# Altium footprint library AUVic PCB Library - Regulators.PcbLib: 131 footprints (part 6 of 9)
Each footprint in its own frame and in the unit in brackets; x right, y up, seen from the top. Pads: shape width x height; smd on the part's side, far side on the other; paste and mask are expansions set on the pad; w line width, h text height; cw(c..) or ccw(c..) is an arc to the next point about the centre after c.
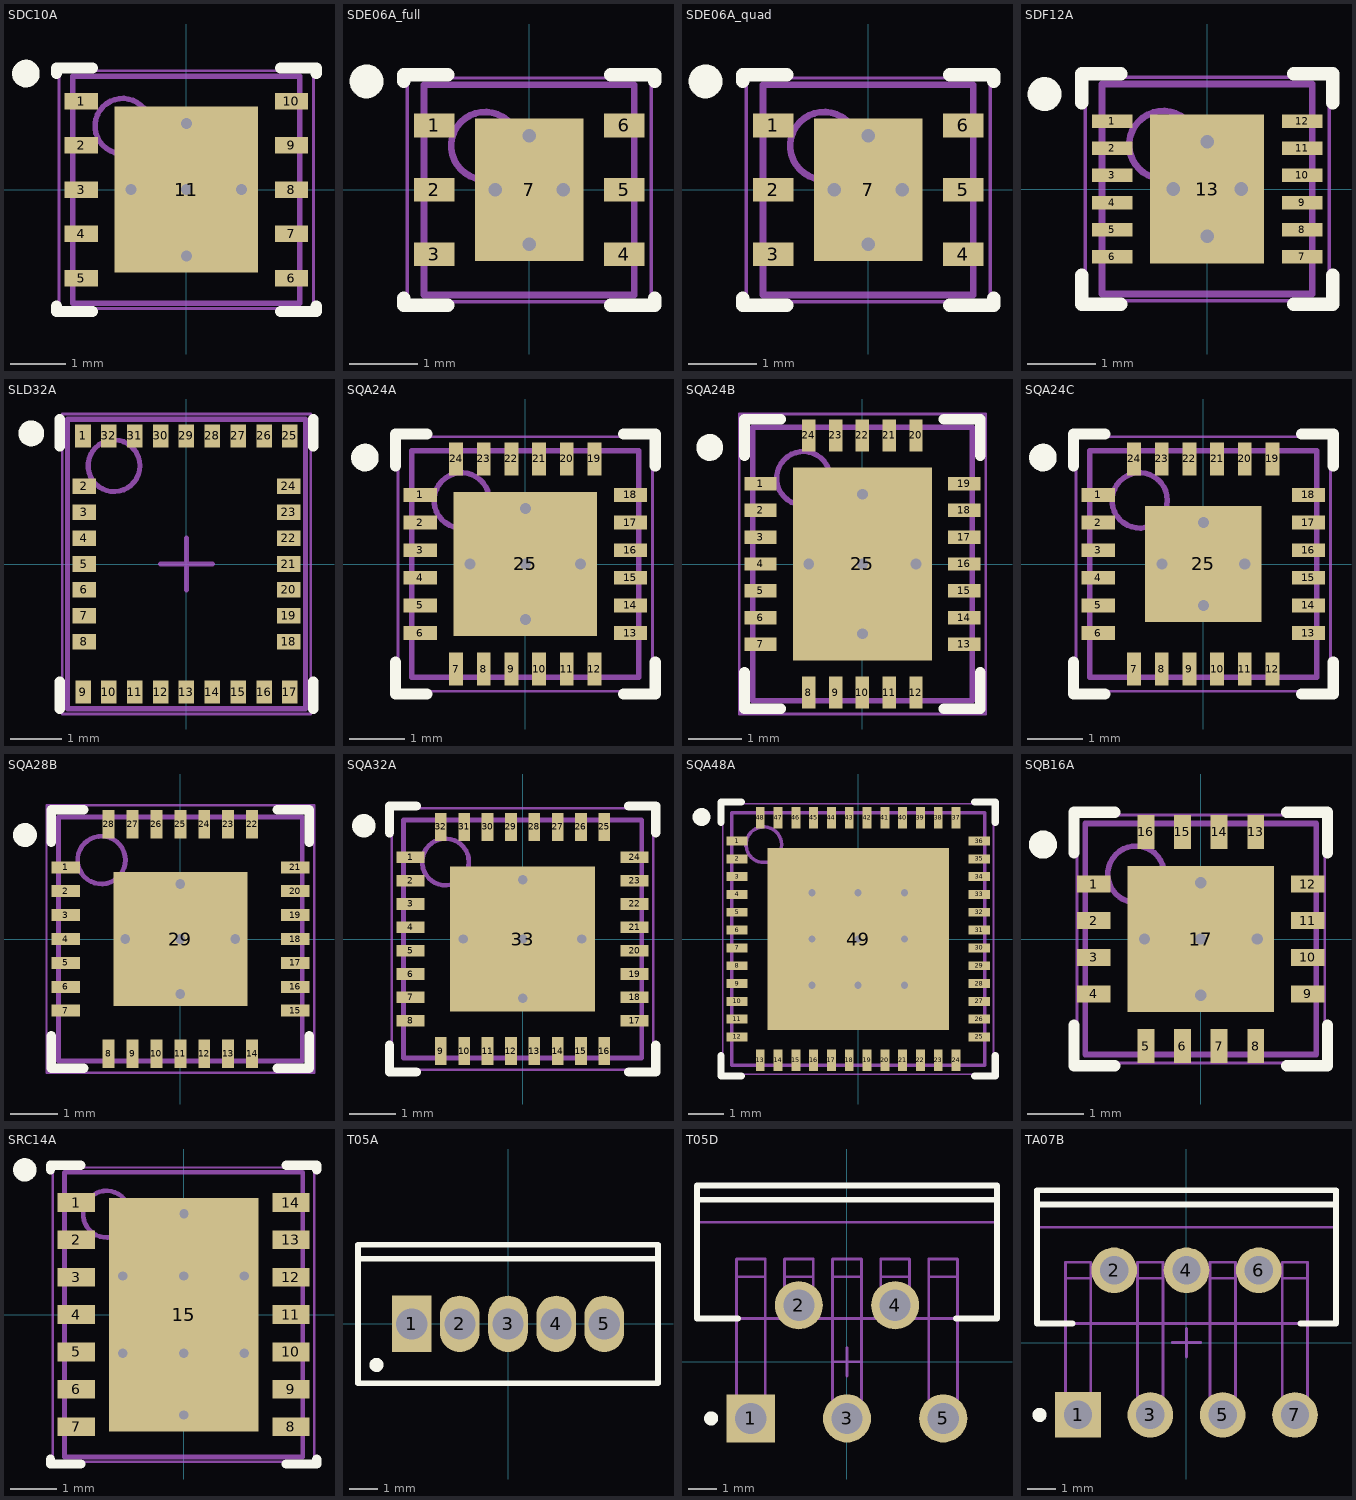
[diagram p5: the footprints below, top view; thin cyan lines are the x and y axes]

## SDC10A [mm] "SON, 10-Leads, Body 4x4 mm, Pitch 0.8mm, NSC Recommended"
height 0.8
pads (11):
  rect 0.6x0.3 smd paste-0.15 mask+0.051: 1(-1.9,1.6) 2(-1.9,0.8) 3(-1.9,0) 4(-1.9,-0.8) 5(-1.9,-1.6) 6(1.9,-1.6) 7(1.9,-0.8) 8(1.9,0) 9(1.9,0.8) 10(1.9,1.6)
  rect 2.6x3 smd paste-1.3 mask+0.051: 11(0,0)
via -1,0 diameter 0.5 hole 0.2
via 0,-1.2 diameter 0.5 hole 0.2
via 0,0 diameter 0.5 hole 0.2
via 0,1.2 diameter 0.5 hole 0.2
via 1,0 diameter 0.5 hole 0.2
Top Overlay:
  circle w0.25: c-2.9,2.1 r0.125
  lines w0.2: -2.35,-2.2 -2.35,-2.1 ; -2.35,2.1 -2.35,2.2 ; -2.345,-2.2 -1.7,-2.2 ; -2.345,2.2 -1.7,2.2 ; 1.7,-2.2 2.345,-2.2 ; 1.7,2.2 2.345,2.2 ; 2.35,-2.2 2.35,-2.1 ; 2.35,2.1 2.35,2.2
Top Paste:
  rectangle: 0.1,-1.4 1.2,-0.1
  region: -0.1,-0.1 -1.2,-0.1 -1.2,-1.4 -0.1,-1.4
  region: -0.1,1.4 -1.2,1.4 -1.2,0.1 -0.1,0.1
  rectangle: 0.1,0.1 1.2,1.4
  rectangle: -2.4,1.45 -1.7,1.75
  rectangle: -2.4,0.65 -1.7,0.95
  rectangle: -2.4,-0.15 -1.7,0.15
  rectangle: -2.4,-0.95 -1.7,-0.65
  rectangle: -2.4,-1.75 -1.7,-1.45
  region: 2.4,-1.45 1.7,-1.45 1.7,-1.75 2.4,-1.75
  region: 2.4,-0.65 1.7,-0.65 1.7,-0.95 2.4,-0.95
  region: 2.4,0.15 1.7,0.15 1.7,-0.15 2.4,-0.15
  region: 2.4,0.95 1.7,0.95 1.7,0.65 2.4,0.65
  region: 2.4,1.75 1.7,1.75 1.7,1.45 2.4,1.45
Mechanical 13:
  circle w0.1: c-1.15,1.15 r0.5
  lines w0.1: -2.05,-2.05 2.05,-2.05 2.05,2.05 -2.05,2.05 -2.05,-2.05
Mechanical 15:
  lines w0.05: -2.3,-2.15 2.3,-2.15 2.3,2.15 -2.3,2.15 -2.3,-2.15
  lines w0.1: -0.5,0 0.5,0 ; 0,-0.5 0,0.5
3D body: height 0.8, standoff 0, extent -2.049,-2.049 2.049,2.049

## SDE06A_full [mm] "SON, 6-Leads, Body 3x3 mm, Pitch 0.95mm, NSC Recommended"
height 0.8
pads (7):
  rect 0.6x0.35 smd paste-0.175 mask+0.051: 1(-1.4,0.95) 2(-1.4,0) 3(-1.4,-0.95) 4(1.4,-0.95) 5(1.4,0) 6(1.4,0.95)
  rect 1.6x2.1 smd paste-0.8 mask+0.051: 7(0,0)
via 0,-0.8 diameter 0.5 hole 0.2
via 0.5,0 diameter 0.5 hole 0.2
via 0,0.8 diameter 0.5 hole 0.2
via -0.5,0 diameter 0.5 hole 0.2
Top Overlay:
  circle w0.25: c-2.4,1.6 r0.125
  lines w0.2: -1.85,-1.6 -1.85,-1.7 -1.2,-1.7 ; -1.85,1.6 -1.85,1.7 -1.2,1.7 ; 1.2,-1.7 1.85,-1.7 1.85,-1.6 ; 1.2,1.7 1.85,1.7 1.85,1.6
Top Paste:
  rectangle: -0.76,-1 0.76,1
  region: 1.9,1.125 1.2,1.125 1.2,0.775 1.9,0.775
  region: 1.9,0.175 1.2,0.175 1.2,-0.175 1.9,-0.175
  region: 1.9,-0.775 1.2,-0.775 1.2,-1.125 1.9,-1.125
  rectangle: -1.9,-1.125 -1.2,-0.775
  rectangle: -1.9,-0.175 -1.2,0.175
  rectangle: -1.9,0.775 -1.2,1.125
Mechanical 13:
  circle w0.1: c-0.65,0.65 r0.5
  lines w0.1: -1.55,-1.55 1.55,-1.55 1.55,1.55 -1.55,1.55 -1.55,-1.55
Mechanical 15:
  lines w0.05: -1.8,-1.65 -1.8,1.65 1.8,1.65 1.8,-1.65 -1.8,-1.65
  lines w0.1: -0.5,0 0.5,0 ; 0,-0.5 0,0.5
3D body: height 0.8, standoff 0, extent -1.55,-1.55 1.55,1.55

## SDE06A_quad [mm] "SON, 6-Leads, Body 3x3 mm, Pitch 0.95mm, NSC Recommended"
height 0.8
pads (7):
  rect 0.6x0.35 smd paste-0.175 mask+0.051: 1(-1.4,0.95) 2(-1.4,0) 3(-1.4,-0.95) 4(1.4,-0.95) 5(1.4,0) 6(1.4,0.95)
  rect 1.6x2.1 smd paste-0.8 mask+0.051: 7(0,0)
via -0.5,0 diameter 0.5 hole 0.2
via 0,0.8 diameter 0.5 hole 0.2
via 0.5,0 diameter 0.5 hole 0.2
via 0,-0.8 diameter 0.5 hole 0.2
Top Overlay:
  circle w0.25: c-2.4,1.6 r0.125
  lines w0.2: -1.85,-1.6 -1.85,-1.7 -1.2,-1.7 ; -1.85,1.6 -1.85,1.7 -1.2,1.7 ; 1.2,-1.7 1.85,-1.7 1.85,-1.6 ; 1.2,1.7 1.85,1.7 1.85,1.6
Top Paste:
  rectangle: -1.9,0.775 -1.2,1.125
  rectangle: -1.9,-0.175 -1.2,0.175
  rectangle: -1.9,-1.125 -1.2,-0.775
  region: 1.9,-0.775 1.2,-0.775 1.2,-1.125 1.9,-1.125
  region: 1.9,0.175 1.2,0.175 1.2,-0.175 1.9,-0.175
  region: 1.9,1.125 1.2,1.125 1.2,0.775 1.9,0.775
  region: -0.1,1.05 -0.8,1.05 -0.8,0.1 -0.1,0.1
  rectangle: 0.1,0.1 0.8,1.05
  rectangle: 0.1,-1.05 0.8,-0.1
  region: -0.1,-0.1 -0.8,-0.1 -0.8,-1.05 -0.1,-1.05
Mechanical 13:
  circle w0.1: c-0.65,0.65 r0.5
  lines w0.1: -1.55,-1.55 -1.55,1.55 1.55,1.55 1.55,-1.55 -1.55,-1.55
Mechanical 15:
  lines w0.05: -1.8,-1.65 1.8,-1.65 1.8,1.65 -1.8,1.65 -1.8,-1.65
  lines w0.1: -0.5,0 0.5,0 ; 0,-0.5 0,0.5
3D body: height 0.8, standoff 0, extent -1.55,-1.55 1.55,1.55

## SDF12A [mm] "SON, 12-Leads, Body 3x3mm, Pitch 0.4mm, NSC Recommended"
height 0.8
pads (13):
  rect 0.6x0.2 smd paste-0.125 mask+0.051: 1(-1.4,1) 2(-1.4,0.6) 3(-1.4,0.2) 4(-1.4,-0.2) 5(-1.4,-0.6) 6(-1.4,-1) 7(1.4,-1) 8(1.4,-0.6) 9(1.4,-0.2) 10(1.4,0.2) 11(1.4,0.6) 12(1.4,1)
  rect 1.68x2.2 smd paste-0.05 mask+0.051: 13(0,0)
via 0,-0.7 diameter 0.5 hole 0.2
via 0,0.7 diameter 0.5 hole 0.2
via 0.5,0 diameter 0.5 hole 0.2
via -0.5,0 diameter 0.5 hole 0.2
Top Overlay:
  circle w0.25: c-2.4,1.4 r0.125
  lines w0.2: -1.85,-1.275 -1.85,-1.7 -1.275,-1.7 ; -1.85,1.275 -1.85,1.7 -1.275,1.7 ; 1.275,-1.7 1.85,-1.7 1.85,-1.275 ; 1.275,1.7 1.85,1.7 1.85,1.275
Top Paste:
  rectangle: -1.9,0.9 -1.2,1.1
  rectangle: -1.9,0.5 -1.2,0.7
  rectangle: -1.9,0.1 -1.2,0.3
  rectangle: -1.9,-0.3 -1.2,-0.1
  rectangle: -1.9,-0.7 -1.2,-0.5
  rectangle: -1.9,-1.1 -1.2,-0.9
  region: 1.9,-0.9 1.2,-0.9 1.2,-1.1 1.9,-1.1
  region: 1.9,-0.5 1.2,-0.5 1.2,-0.7 1.9,-0.7
  region: 1.9,-0.1 1.2,-0.1 1.2,-0.3 1.9,-0.3
  region: 1.9,0.3 1.2,0.3 1.2,0.1 1.9,0.1
  region: 1.9,0.7 1.2,0.7 1.2,0.5 1.9,0.5
  region: 1.9,1.1 1.2,1.1 1.2,0.9 1.9,0.9
Mechanical 13:
  circle w0.1: c-0.65,0.65 r0.5
  lines w0.1: -1.55,-1.55 -1.55,1.55 1.55,1.55 1.55,-1.55 -1.55,-1.55
Mechanical 15:
  lines w0.05: -1.8,-1.65 -1.8,1.65 1.8,1.65 1.8,-1.65 -1.8,-1.65
  lines w0.1: -0.5,0 0.5,0 ; 0,-0.5 0,0.5
3D body: height 0.8, standoff 0, extent -1.55,-1.55 1.55,1.55

## SLD32A [mm] "PQFN, 32-Leads (9x7 pads), Body 4.5x5.5mm, Pitch 0.5mm, NSC Recommended"
height 0.8
pads (32):
  rect 0.3x0.45 smd paste-0.15 mask+0.051: 1(-2,2.475) 9(-2,-2.475) 10(-1.5,-2.475) 11(-1,-2.475) 12(-0.5,-2.475) 13(0,-2.475) 14(0.5,-2.475) 15(1,-2.475) 16(1.5,-2.475) 17(2,-2.475) 25(2,2.475) 26(1.5,2.475) 27(1,2.475) 28(0.5,2.475) 29(0,2.475) 30(-0.5,2.475) 31(-1,2.475) 32(-1.5,2.475)
  rect 0.45x0.3 smd paste-0.15 mask+0.051: 2(-1.975,1.5) 3(-1.975,1) 4(-1.975,0.5) 5(-1.975,0) 6(-1.975,-0.5) 7(-1.975,-1) 8(-1.975,-1.5) 18(1.975,-1.5) 19(1.975,-1) 20(1.975,-0.5) 21(1.975,0) 22(1.975,0.5) 23(1.975,1) 24(1.975,1.5)
Top Overlay:
  circle w0.25: c-3,2.525 r0.125
  lines w0.2: -2.45,-2.8 -2.45,-2.275 ; -2.45,2.275 -2.45,2.8 ; 2.45,-2.8 2.45,-2.275 ; 2.45,2.275 2.45,2.8
Top Paste:
  region: -2.15,2.8 -2.15,2.35 -1.85,2.35 -1.85,2.8
  region: -1.65,2.8 -1.65,2.35 -1.35,2.35 -1.35,2.8
  region: -1.15,2.8 -1.15,2.35 -0.85,2.35 -0.85,2.8
  region: -0.65,2.8 -0.65,2.35 -0.35,2.35 -0.35,2.8
  region: -0.15,2.8 -0.15,2.35 0.15,2.35 0.15,2.8
  region: 0.35,2.8 0.35,2.35 0.65,2.35 0.65,2.8
  region: 0.85,2.8 0.85,2.35 1.15,2.35 1.15,2.8
  region: 1.35,2.8 1.35,2.35 1.65,2.35 1.65,2.8
  region: 1.85,2.8 1.85,2.35 2.15,2.35 2.15,2.8
  region: 2.3,1.65 1.85,1.65 1.85,1.35 2.3,1.35
  region: 2.3,1.15 1.85,1.15 1.85,0.85 2.3,0.85
  region: 2.3,0.65 1.85,0.65 1.85,0.35 2.3,0.35
  region: 2.3,0.15 1.85,0.15 1.85,-0.15 2.3,-0.15
  region: 2.3,-0.35 1.85,-0.35 1.85,-0.65 2.3,-0.65
  region: 2.3,-0.85 1.85,-0.85 1.85,-1.15 2.3,-1.15
  region: 2.3,-1.35 1.85,-1.35 1.85,-1.65 2.3,-1.65
  region: 2.15,-2.8 2.15,-2.35 1.85,-2.35 1.85,-2.8
  region: 1.65,-2.8 1.65,-2.35 1.35,-2.35 1.35,-2.8
  region: 1.15,-2.8 1.15,-2.35 0.85,-2.35 0.85,-2.8
  region: 0.65,-2.8 0.65,-2.35 0.35,-2.35 0.35,-2.8
  region: 0.15,-2.8 0.15,-2.35 -0.15,-2.35 -0.15,-2.8
  region: -0.35,-2.8 -0.35,-2.35 -0.65,-2.35 -0.65,-2.8
  region: -0.85,-2.8 -0.85,-2.35 -1.15,-2.35 -1.15,-2.8
  region: -1.35,-2.8 -1.35,-2.35 -1.65,-2.35 -1.65,-2.8
  region: -1.85,-2.8 -1.85,-2.35 -2.15,-2.35 -2.15,-2.8
  rectangle: -2.3,-1.65 -1.85,-1.35
  rectangle: -2.3,-1.15 -1.85,-0.85
  rectangle: -2.3,-0.65 -1.85,-0.35
  rectangle: -2.3,-0.15 -1.85,0.15
  rectangle: -2.3,0.35 -1.85,0.65
  rectangle: -2.3,0.85 -1.85,1.15
  rectangle: -2.3,1.35 -1.85,1.65
Mechanical 13:
  circle w0.1: c-1.4,1.9 r0.5
  lines w0.1: -2.3,-2.8 2.3,-2.8 2.3,2.8 -2.3,2.8 -2.3,-2.8
Mechanical 15:
  lines w0.05: 2.38,-2.9 -2.4,-2.9 -2.4,2.9 2.38,2.9 ; 2.4,-2.9 2.4,2.9
  lines w0.1: -0.5,0 0.5,0 ; 0,-0.5 0,0.5
3D body: height 0.8, standoff 0, extent -2.299,-2.799 2.299,2.799

## SQA24A [mm] "QFN, 24-Leads, Body 4x4mm, Pitch 0.5mm, NSC Recommended"
height 0.8
pads (25):
  rect 0.6x0.25 smd paste-0.125 mask+0.051: 1(-1.9,1.25) 2(-1.9,0.75) 3(-1.9,0.25) 4(-1.9,-0.25) 5(-1.9,-0.75) 6(-1.9,-1.25) 13(1.9,-1.25) 14(1.9,-0.75) 15(1.9,-0.25) 16(1.9,0.25) 17(1.9,0.75) 18(1.9,1.25)
  rect 0.25x0.6 smd paste-0.125 mask+0.051: 7(-1.25,-1.9) 8(-0.75,-1.9) 9(-0.25,-1.9) 10(0.25,-1.9) 11(0.75,-1.9) 12(1.25,-1.9) 19(1.25,1.9) 20(0.75,1.9) 21(0.25,1.9) 22(-0.25,1.9) 23(-0.75,1.9) 24(-1.25,1.9)
  rect 2.6x2.6 smd paste-1.3 mask+0.051: 25(0,0)
via 0,0 diameter 0.5 hole 0.2
via 1,0 diameter 0.5 hole 0.2
via -1,0 diameter 0.5 hole 0.2
via 0,1 diameter 0.5 hole 0.2
via 0,-1 diameter 0.5 hole 0.2
Top Overlay:
  circle w0.25: c-2.9,1.925 r0.125
  lines w0.2: -2.35,-1.775 -2.35,-2.35 -1.775,-2.35 ; -2.35,1.775 -2.35,2.35 -1.775,2.35 ; 1.775,-2.35 2.35,-2.35 2.35,-1.775 ; 1.775,2.35 2.35,2.35 2.35,1.775
Top Paste:
  region: 1.125,2.4 1.125,1.7 1.375,1.7 1.375,2.4
  region: 0.625,2.4 0.625,1.7 0.875,1.7 0.875,2.4
  region: 0.125,2.4 0.125,1.7 0.375,1.7 0.375,2.4
  region: -0.375,2.4 -0.375,1.7 -0.125,1.7 -0.125,2.4
  region: -0.875,2.4 -0.875,1.7 -0.625,1.7 -0.625,2.4
  region: -1.375,2.4 -1.375,1.7 -1.125,1.7 -1.125,2.4
  region: 2.4,-1.125 1.7,-1.125 1.7,-1.375 2.4,-1.375
  region: 2.4,-0.625 1.7,-0.625 1.7,-0.875 2.4,-0.875
  region: 2.4,-0.125 1.7,-0.125 1.7,-0.375 2.4,-0.375
  region: 2.4,0.375 1.7,0.375 1.7,0.125 2.4,0.125
  region: 2.4,0.875 1.7,0.875 1.7,0.625 2.4,0.625
  region: 2.4,1.375 1.7,1.375 1.7,1.125 2.4,1.125
  region: -1.125,-2.4 -1.125,-1.7 -1.375,-1.7 -1.375,-2.4
  region: -0.625,-2.4 -0.625,-1.7 -0.875,-1.7 -0.875,-2.4
  region: -0.125,-2.4 -0.125,-1.7 -0.375,-1.7 -0.375,-2.4
  region: 0.375,-2.4 0.375,-1.7 0.125,-1.7 0.125,-2.4
  region: 0.875,-2.4 0.875,-1.7 0.625,-1.7 0.625,-2.4
  region: 1.375,-2.4 1.375,-1.7 1.125,-1.7 1.125,-2.4
  rectangle: -2.4,-1.375 -1.7,-1.125
  rectangle: -2.4,-0.875 -1.7,-0.625
  rectangle: -2.4,-0.375 -1.7,-0.125
  rectangle: -2.4,0.125 -1.7,0.375
  rectangle: -2.4,0.625 -1.7,0.875
  rectangle: -2.4,1.125 -1.7,1.375
  rectangle: 0.1,-1.2 1.2,-0.1
  region: -0.1,-0.1 -1.2,-0.1 -1.2,-1.2 -0.1,-1.2
  region: -0.1,1.2 -1.2,1.2 -1.2,0.1 -0.1,0.1
  rectangle: 0.1,0.1 1.2,1.2
Mechanical 13:
  circle w0.1: c-1.15,1.15 r0.5
  lines w0.1: -2.05,-2.05 -2.05,2.05 2.05,2.05 2.05,-2.05 -2.05,-2.05
Mechanical 15:
  lines w0.05: -2.3,-2.3 -2.3,2.3 2.3,2.3 2.3,-2.3 -2.3,-2.3
  lines w0.1: -0.5,0 0.5,0 ; 0,-0.5 0,0.5
3D body: height 0.8, standoff 0, extent -2.05,-2.05 2.05,2.05

## SQA24B [mm] "QFN, 24-Leads, Body 5x4mm, Pitch 0.5mm, NSC Recommended"
height 0.8
pads (25):
  rect 0.6x0.25 smd paste-0.3 mask+0.051: 1(-1.9,1.5) 2(-1.9,1) 3(-1.9,0.5) 4(-1.9,0) 5(-1.9,-0.5) 6(-1.9,-1) 7(-1.9,-1.5) 13(1.9,-1.5) 14(1.9,-1) 15(1.9,-0.5) 16(1.9,0) 17(1.9,0.5) 18(1.9,1) 19(1.9,1.5)
  rect 0.25x0.6 smd paste-0.3 mask+0.051: 8(-1,-2.4) 9(-0.5,-2.4) 10(0,-2.4) 11(0.5,-2.4) 12(1,-2.4) 20(1,2.4) 21(0.5,2.4) 22(0,2.4) 23(-0.5,2.4) 24(-1,2.4)
  rect 2.6x3.6 smd paste-1.3 mask+0.051: 25(0,0)
via 0,0 diameter 0.5 hole 0.2
via -1,0 diameter 0.5 hole 0.2
via 0,-1.3 diameter 0.5 hole 0.2
via 0,1.3 diameter 0.5 hole 0.2
via 1,0 diameter 0.5 hole 0.2
Top Overlay:
  circle w0.25: c-2.85,2.175 r0.125
  lines w0.2: -2.2,-2.025 -2.2,-2.7 -1.525,-2.7 ; -2.2,2.025 -2.2,2.7 -1.525,2.7 ; 1.525,-2.7 2.2,-2.7 2.2,-2.025 ; 1.525,2.7 2.2,2.7 2.2,2.025
Top Paste:
  region: 1.125,-2.9 1.125,-2.2 0.875,-2.2 0.875,-2.9
  region: 0.625,-2.9 0.625,-2.2 0.375,-2.2 0.375,-2.9
  region: 0.125,-2.9 0.125,-2.2 -0.125,-2.2 -0.125,-2.9
  region: -0.375,-2.9 -0.375,-2.2 -0.625,-2.2 -0.625,-2.9
  region: -0.875,-2.9 -0.875,-2.2 -1.125,-2.2 -1.125,-2.9
  rectangle: -2.4,-1.625 -1.7,-1.375
  rectangle: -2.4,-1.125 -1.7,-0.875
  rectangle: -2.4,-0.625 -1.7,-0.375
  rectangle: -2.4,-0.125 -1.7,0.125
  rectangle: -2.4,0.375 -1.7,0.625
  rectangle: -2.4,0.875 -1.7,1.125
  rectangle: -2.4,1.375 -1.7,1.625
  region: -1.125,2.9 -1.125,2.2 -0.875,2.2 -0.875,2.9
  region: -0.625,2.9 -0.625,2.2 -0.375,2.2 -0.375,2.9
  region: -0.125,2.9 -0.125,2.2 0.125,2.2 0.125,2.9
  region: 0.375,2.9 0.375,2.2 0.625,2.2 0.625,2.9
  region: 0.875,2.9 0.875,2.2 1.125,2.2 1.125,2.9
  region: 2.4,-1.375 1.7,-1.375 1.7,-1.625 2.4,-1.625
  region: 2.4,-0.875 1.7,-0.875 1.7,-1.125 2.4,-1.125
  region: 2.4,-0.375 1.7,-0.375 1.7,-0.625 2.4,-0.625
  region: 2.4,0.125 1.7,0.125 1.7,-0.125 2.4,-0.125
  region: 2.4,0.625 1.7,0.625 1.7,0.375 2.4,0.375
  region: 2.4,1.125 1.7,1.125 1.7,0.875 2.4,0.875
  region: 2.4,1.625 1.7,1.625 1.7,1.375 2.4,1.375
  rectangle: 0.1,0.1 1.2,1.7
  region: -0.1,1.7 -1.2,1.7 -1.2,0.1 -0.1,0.1
  region: -0.1,-0.1 -1.2,-0.1 -1.2,-1.7 -0.1,-1.7
  rectangle: 0.1,-1.7 1.2,-0.1
Mechanical 13:
  circle w0.1: c-1.1,1.6 r0.5
  lines w0.1: -2.05,-2.55 2.05,-2.55 2.05,2.55 -2.05,2.55 -2.05,-2.55
Mechanical 15:
  lines w0.05: -2.3,-2.8 2.3,-2.8 2.3,2.8 -2.3,2.8 -2.3,-2.8
  lines w0.1: -0.5,0 0.5,0 ; 0,-0.5 0,0.5
3D body: height 0.8, standoff 0, extent -2.05,-2.55 2.05,2.55

## SQA24C [mm] "QFN, 24-Leads, Body 4x4mm, Pitch 0.5mm, NSC Recommended"
height 0.8
pads (25):
  rect 0.6x0.25 smd paste-0.125 mask+0.051: 1(-1.9,1.25) 2(-1.9,0.75) 3(-1.9,0.25) 4(-1.9,-0.25) 5(-1.9,-0.75) 6(-1.9,-1.25) 13(1.9,-1.25) 14(1.9,-0.75) 15(1.9,-0.25) 16(1.9,0.25) 17(1.9,0.75) 18(1.9,1.25)
  rect 0.25x0.6 smd paste-0.125 mask+0.051: 7(-1.25,-1.9) 8(-0.75,-1.9) 9(-0.25,-1.9) 10(0.25,-1.9) 11(0.75,-1.9) 12(1.25,-1.9) 19(1.25,1.9) 20(0.75,1.9) 21(0.25,1.9) 22(-0.25,1.9) 23(-0.75,1.9) 24(-1.25,1.9)
  rect 2.1x2.1 smd paste-1.05 mask+0.051: 25(0,0)
via 0.75,0 diameter 0.5 hole 0.2
via -0.75,0 diameter 0.5 hole 0.2
via 0,0.75 diameter 0.5 hole 0.2
via 0,-0.75 diameter 0.5 hole 0.2
Top Overlay:
  circle w0.25: c-2.9,1.925 r0.125
  lines w0.2: -2.35,-1.775 -2.35,-2.35 -1.775,-2.35 ; -2.35,1.775 -2.35,2.35 -1.775,2.35 ; 1.775,-2.35 2.35,-2.35 2.35,-1.775 ; 1.775,2.35 2.35,2.35 2.35,1.775
Top Paste:
  rectangle: -0.95,-0.95 0.95,0.95
  region: 1.125,2.4 1.125,1.7 1.375,1.7 1.375,2.4
  region: 0.625,2.4 0.625,1.7 0.875,1.7 0.875,2.4
  region: 0.125,2.4 0.125,1.7 0.375,1.7 0.375,2.4
  region: -0.375,2.4 -0.375,1.7 -0.125,1.7 -0.125,2.4
  region: -0.875,2.4 -0.875,1.7 -0.625,1.7 -0.625,2.4
  region: -1.375,2.4 -1.375,1.7 -1.125,1.7 -1.125,2.4
  region: 2.4,-1.125 1.7,-1.125 1.7,-1.375 2.4,-1.375
  region: 2.4,-0.625 1.7,-0.625 1.7,-0.875 2.4,-0.875
  region: 2.4,-0.125 1.7,-0.125 1.7,-0.375 2.4,-0.375
  region: 2.4,0.375 1.7,0.375 1.7,0.125 2.4,0.125
  region: 2.4,0.875 1.7,0.875 1.7,0.625 2.4,0.625
  region: 2.4,1.375 1.7,1.375 1.7,1.125 2.4,1.125
  region: -1.125,-2.4 -1.125,-1.7 -1.375,-1.7 -1.375,-2.4
  region: -0.625,-2.4 -0.625,-1.7 -0.875,-1.7 -0.875,-2.4
  region: -0.125,-2.4 -0.125,-1.7 -0.375,-1.7 -0.375,-2.4
  region: 0.375,-2.4 0.375,-1.7 0.125,-1.7 0.125,-2.4
  region: 0.875,-2.4 0.875,-1.7 0.625,-1.7 0.625,-2.4
  region: 1.375,-2.4 1.375,-1.7 1.125,-1.7 1.125,-2.4
  rectangle: -2.4,-1.375 -1.7,-1.125
  rectangle: -2.4,-0.875 -1.7,-0.625
  rectangle: -2.4,-0.375 -1.7,-0.125
  rectangle: -2.4,0.125 -1.7,0.375
  rectangle: -2.4,0.625 -1.7,0.875
  rectangle: -2.4,1.125 -1.7,1.375
Mechanical 13:
  circle w0.1: c-1.15,1.15 r0.5
  lines w0.1: -2.05,-2.05 -2.05,2.05 2.05,2.05 2.05,-2.05 -2.05,-2.05
Mechanical 15:
  lines w0.05: -2.3,-2.3 -2.3,2.3 2.3,2.3 2.3,-2.3 -2.3,-2.3
  lines w0.1: -0.5,0 0.5,0 ; 0,-0.5 0,0.5
3D body: height 0.8, standoff 0, extent -2.05,-2.05 2.05,2.05

## SQA28B [mm] "QFN, 29-Leads, Body 5x5mm, Pitch 0.5mm, Thermal Pad 2.8x2.8mm, NSC Recommended"
height 0.8
pads (29):
  rect 0.6x0.25 smd paste-0.125 mask+0.051: 1(-2.4,1.5) 2(-2.4,1) 3(-2.4,0.5) 4(-2.4,0) 5(-2.4,-0.5) 6(-2.4,-1) 7(-2.4,-1.5) 15(2.4,-1.5) 16(2.4,-1) 17(2.4,-0.5) 18(2.4,0) 19(2.4,0.5) 20(2.4,1) 21(2.4,1.5)
  rect 0.25x0.6 smd paste-0.125 mask+0.051: 8(-1.5,-2.4) 9(-1,-2.4) 10(-0.5,-2.4) 11(0,-2.4) 12(0.5,-2.4) 13(1,-2.4) 14(1.5,-2.4) 22(1.5,2.4) 23(1,2.4) 24(0.5,2.4) 25(0,2.4) 26(-0.5,2.4) 27(-1,2.4) 28(-1.5,2.4)
  rect 2.8x2.8 smd paste-1.8 mask+0.051: 29(0,0)
via -1.15,0 diameter 0.5 hole 0.2
via 0,-1.15 diameter 0.5 hole 0.2
via 0,1.15 diameter 0.5 hole 0.2
via 1.15,0 diameter 0.5 hole 0.2
via 0,0 diameter 0.5 hole 0.2
Top Overlay:
  circle w0.25: c-3.25,2.175 r0.125
  lines w0.2: -2.7,-2.025 -2.7,-2.7 -2.025,-2.7 ; -2.7,2.025 -2.7,2.7 -2.025,2.7 ; 2.025,-2.7 2.7,-2.7 2.7,-2.025 ; 2.025,2.7 2.7,2.7 2.7,2.025
Top Paste:
  region: 1.2,0.1 1.2,1.2 0.1,1.2 0.1,0.1
  rectangle: 0.1,-1.2 1.2,-0.1
  region: -1.2,-0.1 -1.2,-1.2 -0.1,-1.2 -0.1,-0.1
  region: -0.1,1.2 -1.2,1.2 -1.2,0.1 -0.1,0.1
  region: -1.375,-2.9 -1.375,-2.2 -1.625,-2.2 -1.625,-2.9
  region: -0.875,-2.9 -0.875,-2.2 -1.125,-2.2 -1.125,-2.9
  region: -0.375,-2.9 -0.375,-2.2 -0.625,-2.2 -0.625,-2.9
  region: 0.125,-2.9 0.125,-2.2 -0.125,-2.2 -0.125,-2.9
  region: 0.625,-2.9 0.625,-2.2 0.375,-2.2 0.375,-2.9
  region: 1.125,-2.9 1.125,-2.2 0.875,-2.2 0.875,-2.9
  region: 1.625,-2.9 1.625,-2.2 1.375,-2.2 1.375,-2.9
  region: -1.625,2.9 -1.625,2.2 -1.375,2.2 -1.375,2.9
  region: -1.125,2.9 -1.125,2.2 -0.875,2.2 -0.875,2.9
  region: -0.625,2.9 -0.625,2.2 -0.375,2.2 -0.375,2.9
  region: -0.125,2.9 -0.125,2.2 0.125,2.2 0.125,2.9
  region: 0.375,2.9 0.375,2.2 0.625,2.2 0.625,2.9
  region: 0.875,2.9 0.875,2.2 1.125,2.2 1.125,2.9
  region: 1.375,2.9 1.375,2.2 1.625,2.2 1.625,2.9
  region: 2.9,1.625 2.2,1.625 2.2,1.375 2.9,1.375
  region: 2.9,1.125 2.2,1.125 2.2,0.875 2.9,0.875
  region: 2.9,0.625 2.2,0.625 2.2,0.375 2.9,0.375
  region: 2.9,0.125 2.2,0.125 2.2,-0.125 2.9,-0.125
  region: 2.9,-0.375 2.2,-0.375 2.2,-0.625 2.9,-0.625
  region: 2.9,-0.875 2.2,-0.875 2.2,-1.125 2.9,-1.125
  region: 2.9,-1.375 2.2,-1.375 2.2,-1.625 2.9,-1.625
  rectangle: -2.9,-1.625 -2.2,-1.375
  rectangle: -2.9,-1.125 -2.2,-0.875
  rectangle: -2.9,-0.625 -2.2,-0.375
  rectangle: -2.9,-0.125 -2.2,0.125
  rectangle: -2.9,0.375 -2.2,0.625
  rectangle: -2.9,0.875 -2.2,1.125
  rectangle: -2.9,1.375 -2.2,1.625
Mechanical 13:
  circle w0.1: c-1.65,1.65 r0.5
  lines w0.1: -2.55,-2.55 -2.55,2.55 2.55,2.55 2.55,-2.55 -2.55,-2.55
Mechanical 15:
  lines w0.05: -2.8,-2.8 -2.8,2.8 2.8,2.8 2.8,-2.8 -2.8,-2.8
  lines w0.1: -0.5,0 0.5,0 ; 0,-0.5 0,0.5
3D body: height 0.8, standoff 0, extent -2.55,-2.55 2.55,2.55

## SQA32A [mm] "QFN, 32-Leads, Body 5x5mm, Pitch 0.5mm, NSC Recommended"
height 0.8
pads (33):
  rect 0.6x0.25 smd paste-0.125 mask+0.051: 1(-2.4,1.75) 2(-2.4,1.25) 3(-2.4,0.75) 4(-2.4,0.25) 5(-2.4,-0.25) 6(-2.4,-0.75) 7(-2.4,-1.25) 8(-2.4,-1.75) 17(2.4,-1.75) 18(2.4,-1.25) 19(2.4,-0.75) 20(2.4,-0.25) 21(2.4,0.25) 22(2.4,0.75) 23(2.4,1.25) 24(2.4,1.75)
  rect 0.25x0.6 smd paste-0.125 mask+0.051: 9(-1.75,-2.4) 10(-1.25,-2.4) 11(-0.75,-2.4) 12(-0.25,-2.4) 13(0.25,-2.4) 14(0.75,-2.4) 15(1.25,-2.4) 16(1.75,-2.4) 25(1.75,2.4) 26(1.25,2.4) 27(0.75,2.4) 28(0.25,2.4) 29(-0.25,2.4) 30(-0.75,2.4) 31(-1.25,2.4) 32(-1.75,2.4)
  rect 3.1x3.1 smd paste-1.55 mask+0.051: 33(0,0)
via 0,1.27 diameter 0.5 hole 0.2
via -1.27,0 diameter 0.5 hole 0.2
via 0,0 diameter 0.5 hole 0.2
via 1.27,0 diameter 0.5 hole 0.2
via 0,-1.27 diameter 0.5 hole 0.2
Top Overlay:
  circle w0.25: c-3.4,2.425 r0.125
  lines w0.2: -2.85,-2.275 -2.85,-2.85 -2.275,-2.85 ; -2.85,2.275 -2.85,2.85 -2.275,2.85 ; 2.275,-2.85 2.85,-2.85 2.85,-2.275 ; 2.275,2.85 2.85,2.85 2.85,2.275
Top Paste:
  region: 1.625,2.9 1.625,2.2 1.875,2.2 1.875,2.9
  region: 1.125,2.9 1.125,2.2 1.375,2.2 1.375,2.9
  region: 0.625,2.9 0.625,2.2 0.875,2.2 0.875,2.9
  region: 0.125,2.9 0.125,2.2 0.375,2.2 0.375,2.9
  region: -0.375,2.9 -0.375,2.2 -0.125,2.2 -0.125,2.9
  region: -0.875,2.9 -0.875,2.2 -0.625,2.2 -0.625,2.9
  region: -1.375,2.9 -1.375,2.2 -1.125,2.2 -1.125,2.9
  region: -1.875,2.9 -1.875,2.2 -1.625,2.2 -1.625,2.9
  region: 2.9,-1.625 2.2,-1.625 2.2,-1.875 2.9,-1.875
  region: 2.9,-1.125 2.2,-1.125 2.2,-1.375 2.9,-1.375
  region: 2.9,-0.625 2.2,-0.625 2.2,-0.875 2.9,-0.875
  region: 2.9,-0.125 2.2,-0.125 2.2,-0.375 2.9,-0.375
  region: 2.9,0.375 2.2,0.375 2.2,0.125 2.9,0.125
  region: 2.9,0.875 2.2,0.875 2.2,0.625 2.9,0.625
  region: 2.9,1.375 2.2,1.375 2.2,1.125 2.9,1.125
  region: 2.9,1.875 2.2,1.875 2.2,1.625 2.9,1.625
  region: -1.625,-2.9 -1.625,-2.2 -1.875,-2.2 -1.875,-2.9
  region: -1.125,-2.9 -1.125,-2.2 -1.375,-2.2 -1.375,-2.9
  region: -0.625,-2.9 -0.625,-2.2 -0.875,-2.2 -0.875,-2.9
  region: -0.125,-2.9 -0.125,-2.2 -0.375,-2.2 -0.375,-2.9
  region: 0.375,-2.9 0.375,-2.2 0.125,-2.2 0.125,-2.9
  region: 0.875,-2.9 0.875,-2.2 0.625,-2.2 0.625,-2.9
  region: 1.375,-2.9 1.375,-2.2 1.125,-2.2 1.125,-2.9
  region: 1.875,-2.9 1.875,-2.2 1.625,-2.2 1.625,-2.9
  rectangle: -2.9,-1.875 -2.2,-1.625
  rectangle: -2.9,-1.375 -2.2,-1.125
  rectangle: -2.9,-0.875 -2.2,-0.625
  rectangle: -2.9,-0.375 -2.2,-0.125
  rectangle: -2.9,0.125 -2.2,0.375
  rectangle: -2.9,0.625 -2.2,0.875
  rectangle: -2.9,1.125 -2.2,1.375
  rectangle: -2.9,1.625 -2.2,1.875
  rectangle: 0.1,0.1 1.4,1.4
  region: -0.1,1.4 -1.4,1.4 -1.4,0.1 -0.1,0.1
  region: -0.1,-0.1 -1.4,-0.1 -1.4,-1.4 -0.1,-1.4
  rectangle: 0.1,-1.4 1.4,-0.1
Mechanical 13:
  circle w0.1: c-1.65,1.65 r0.5
  lines w0.1: -2.55,-2.55 -2.55,2.55 2.55,2.55 2.55,-2.55 -2.55,-2.55
Mechanical 15:
  lines w0.05: -2.8,-2.8 -2.8,2.8 2.8,2.8 2.8,-2.8 -2.8,-2.8
  lines w0.1: -0.5,0 0.5,0 ; 0,-0.5 0,0.5
3D body: height 0.8, standoff 0, extent -2.55,-2.55 2.55,2.55

## SQA48A [mm] "QFN, 48-Leads, Body 7x7mm, Pitch 0.5mm, NSC Recommended"
height 0.8
pads (49):
  rect 0.6x0.25 smd paste-0.125 mask+0.051: 1(-3.4,2.75) 2(-3.4,2.25) 3(-3.4,1.75) 4(-3.4,1.25) 5(-3.4,0.75) 6(-3.4,0.25) 7(-3.4,-0.25) 8(-3.4,-0.75) 9(-3.4,-1.25) 10(-3.4,-1.75) 11(-3.4,-2.25) 12(-3.4,-2.75) 25(3.4,-2.75) 26(3.4,-2.25) 27(3.4,-1.75) 28(3.4,-1.25) 29(3.4,-0.75) 30(3.4,-0.25) 31(3.4,0.25) 32(3.4,0.75) 33(3.4,1.25) 34(3.4,1.75) 35(3.4,2.25) 36(3.4,2.75)
  rect 0.25x0.6 smd paste-0.125 mask+0.051: 13(-2.75,-3.4) 14(-2.25,-3.4) 15(-1.75,-3.4) 16(-1.25,-3.4) 17(-0.75,-3.4) 18(-0.25,-3.4) 19(0.25,-3.4) 20(0.75,-3.4) 21(1.25,-3.4) 22(1.75,-3.4) 23(2.25,-3.4) 24(2.75,-3.4) 37(2.75,3.4) 38(2.25,3.4) 39(1.75,3.4) 40(1.25,3.4) 41(0.75,3.4) 42(0.25,3.4) 43(-0.25,3.4) 44(-0.75,3.4) 45(-1.25,3.4) 46(-1.75,3.4) 47(-2.25,3.4) 48(-2.75,3.4)
  rect 5.1x5.1 smd paste-2.55 mask+0.051: 49(0,0)
via 0,-1.3 diameter 0.5 hole 0.2
via 1.3,-1.3 diameter 0.5 hole 0.2
via -1.3,-1.3 diameter 0.5 hole 0.2
via 0,1.3 diameter 0.5 hole 0.2
via 1.3,1.3 diameter 0.5 hole 0.2
via -1.3,1.3 diameter 0.5 hole 0.2
via -1.3,0 diameter 0.5 hole 0.2
via 1.3,0 diameter 0.5 hole 0.2
via 0,0 diameter 0.5 hole 0.2
Top Overlay:
  circle w0.25: c-4.4,3.425 r0.125
  lines w0.2: -3.85,-3.275 -3.85,-3.85 -3.275,-3.85 ; -3.85,3.275 -3.85,3.85 -3.275,3.85 ; 3.275,-3.85 3.85,-3.85 3.85,-3.275 ; 3.275,3.85 3.85,3.85 3.85,3.275
Top Paste:
  rectangle: -3.9,2.625 -3.2,2.875
  rectangle: -3.9,2.125 -3.2,2.375
  rectangle: -3.9,1.625 -3.2,1.875
  rectangle: -3.9,1.125 -3.2,1.375
  rectangle: -3.9,0.625 -3.2,0.875
  rectangle: -3.9,0.125 -3.2,0.375
  rectangle: -3.9,-0.375 -3.2,-0.125
  rectangle: -3.9,-0.875 -3.2,-0.625
  rectangle: -3.9,-1.375 -3.2,-1.125
  rectangle: -3.9,-1.875 -3.2,-1.625
  rectangle: -3.9,-2.375 -3.2,-2.125
  rectangle: -3.9,-2.875 -3.2,-2.625
  region: 2.875,-3.9 2.875,-3.2 2.625,-3.2 2.625,-3.9
  region: 2.375,-3.9 2.375,-3.2 2.125,-3.2 2.125,-3.9
  region: 1.875,-3.9 1.875,-3.2 1.625,-3.2 1.625,-3.9
  region: 1.375,-3.9 1.375,-3.2 1.125,-3.2 1.125,-3.9
  region: 0.875,-3.9 0.875,-3.2 0.625,-3.2 0.625,-3.9
  region: 0.375,-3.9 0.375,-3.2 0.125,-3.2 0.125,-3.9
  region: -0.125,-3.9 -0.125,-3.2 -0.375,-3.2 -0.375,-3.9
  region: -0.625,-3.9 -0.625,-3.2 -0.875,-3.2 -0.875,-3.9
  region: -1.125,-3.9 -1.125,-3.2 -1.375,-3.2 -1.375,-3.9
  region: -1.625,-3.9 -1.625,-3.2 -1.875,-3.2 -1.875,-3.9
  region: -2.125,-3.9 -2.125,-3.2 -2.375,-3.2 -2.375,-3.9
  region: -2.625,-3.9 -2.625,-3.2 -2.875,-3.2 -2.875,-3.9
  region: 3.9,2.875 3.2,2.875 3.2,2.625 3.9,2.625
  region: 3.9,2.375 3.2,2.375 3.2,2.125 3.9,2.125
  region: 3.9,1.875 3.2,1.875 3.2,1.625 3.9,1.625
  region: 3.9,1.375 3.2,1.375 3.2,1.125 3.9,1.125
  region: 3.9,0.875 3.2,0.875 3.2,0.625 3.9,0.625
  region: 3.9,0.375 3.2,0.375 3.2,0.125 3.9,0.125
  region: 3.9,-0.125 3.2,-0.125 3.2,-0.375 3.9,-0.375
  region: 3.9,-0.625 3.2,-0.625 3.2,-0.875 3.9,-0.875
  region: 3.9,-1.125 3.2,-1.125 3.2,-1.375 3.9,-1.375
  region: 3.9,-1.625 3.2,-1.625 3.2,-1.875 3.9,-1.875
  region: 3.9,-2.125 3.2,-2.125 3.2,-2.375 3.9,-2.375
  region: 3.9,-2.625 3.2,-2.625 3.2,-2.875 3.9,-2.875
  region: -2.875,3.9 -2.875,3.2 -2.625,3.2 -2.625,3.9
  region: -2.375,3.9 -2.375,3.2 -2.125,3.2 -2.125,3.9
  region: -1.875,3.9 -1.875,3.2 -1.625,3.2 -1.625,3.9
  region: -1.375,3.9 -1.375,3.2 -1.125,3.2 -1.125,3.9
  region: -0.875,3.9 -0.875,3.2 -0.625,3.2 -0.625,3.9
  region: -0.375,3.9 -0.375,3.2 -0.125,3.2 -0.125,3.9
  region: 0.125,3.9 0.125,3.2 0.375,3.2 0.375,3.9
  region: 0.625,3.9 0.625,3.2 0.875,3.2 0.875,3.9
  region: 1.125,3.9 1.125,3.2 1.375,3.2 1.375,3.9
  region: 1.625,3.9 1.625,3.2 1.875,3.2 1.875,3.9
  region: 2.125,3.9 2.125,3.2 2.375,3.2 2.375,3.9
  region: 2.625,3.9 2.625,3.2 2.875,3.2 2.875,3.9
  rectangle: 0.1,0.1 1.2,1.2
  rectangle: 0.1,1.4 1.2,2.5
  rectangle: 1.4,0.1 2.5,1.2
  rectangle: 1.4,1.4 2.5,2.5
  region: -1.4,2.5 -2.5,2.5 -2.5,1.4 -1.4,1.4
  region: -1.4,1.2 -2.5,1.2 -2.5,0.1 -1.4,0.1
  region: -0.1,2.5 -1.2,2.5 -1.2,1.4 -0.1,1.4
  region: -0.1,1.2 -1.2,1.2 -1.2,0.1 -0.1,0.1
  region: -2.5,-1.4 -2.5,-2.5 -1.4,-2.5 -1.4,-1.4
  region: -1.2,-1.4 -1.2,-2.5 -0.1,-2.5 -0.1,-1.4
  region: -2.5,-0.1 -2.5,-1.2 -1.4,-1.2 -1.4,-0.1
  region: -1.2,-0.1 -1.2,-1.2 -0.1,-1.2 -0.1,-0.1
  region: 1.4,-1.4 1.4,-2.5 2.5,-2.5 2.5,-1.4
  region: 0.1,-1.4 0.1,-2.5 1.2,-2.5 1.2,-1.4
  region: 1.4,-0.1 1.4,-1.2 2.5,-1.2 2.5,-0.1
  region: 0.1,-0.1 0.1,-1.2 1.2,-1.2 1.2,-0.1
Mechanical 13:
  circle w0.1: c-2.65,2.65 r0.5
  lines w0.1: -3.55,-3.55 3.55,-3.55 3.55,3.55 -3.55,3.55 -3.55,-3.55
Mechanical 15:
  lines w0.05: -3.8,-3.8 3.8,-3.8 3.8,3.8 -3.8,3.8 -3.8,-3.8
  lines w0.1: -0.5,0 0.5,0 ; 0,-0.5 0,0.5
3D body: height 0.8, standoff 0, extent -3.55,-3.55 3.55,3.55

## SQB16A [mm] "QFN, 16-Leads, Body 4x4mm, Pitch 0.65mm, Thermal Pad 2.6x2.6mm, NSC Recommended"
height 0.8
pads (17):
  rect 0.6x0.3 smd paste-0.15 mask+0.051: 1(-1.9,0.975) 2(-1.9,0.325) 3(-1.9,-0.325) 4(-1.9,-0.975) 9(1.9,-0.975) 10(1.9,-0.325) 11(1.9,0.325) 12(1.9,0.975)
  rect 0.3x0.6 smd paste-0.15 mask+0.051: 5(-0.975,-1.9) 6(-0.325,-1.9) 7(0.325,-1.9) 8(0.975,-1.9) 13(0.975,1.9) 14(0.325,1.9) 15(-0.325,1.9) 16(-0.975,1.9)
  rect 2.6x2.6 smd paste-1.3 mask+0.051: 17(0,0)
via 0,0 diameter 0.5 hole 0.2
via 1,0 diameter 0.5 hole 0.2
via -1,0 diameter 0.5 hole 0.2
via 0,1 diameter 0.5 hole 0.2
via 0,-1 diameter 0.5 hole 0.2
Top Overlay:
  circle w0.25: c-2.8,1.675 r0.125
  lines w0.2: -2.25,-1.525 -2.25,-2.25 -1.525,-2.25 ; -2.25,1.525 -2.25,2.25 -1.525,2.25 ; 1.525,-2.25 2.25,-2.25 2.25,-1.525 ; 1.525,2.25 2.25,2.25 2.25,1.525
Top Paste:
  rectangle: -2.4,0.825 -1.7,1.125
  rectangle: -2.4,0.175 -1.7,0.475
  rectangle: -2.4,-0.475 -1.7,-0.175
  rectangle: -2.4,-1.125 -1.7,-0.825
  region: 1.125,-2.4 1.125,-1.7 0.825,-1.7 0.825,-2.4
  region: 0.475,-2.4 0.475,-1.7 0.175,-1.7 0.175,-2.4
  region: -0.175,-2.4 -0.175,-1.7 -0.475,-1.7 -0.475,-2.4
  region: -0.825,-2.4 -0.825,-1.7 -1.125,-1.7 -1.125,-2.4
  region: 2.4,1.125 1.7,1.125 1.7,0.825 2.4,0.825
  region: 2.4,0.475 1.7,0.475 1.7,0.175 2.4,0.175
  region: 2.4,-0.175 1.7,-0.175 1.7,-0.475 2.4,-0.475
  region: 2.4,-0.825 1.7,-0.825 1.7,-1.125 2.4,-1.125
  region: -1.125,2.4 -1.125,1.7 -0.825,1.7 -0.825,2.4
  region: -0.475,2.4 -0.475,1.7 -0.175,1.7 -0.175,2.4
  region: 0.175,2.4 0.175,1.7 0.475,1.7 0.475,2.4
  region: 0.825,2.4 0.825,1.7 1.125,1.7 1.125,2.4
  rectangle: 0.1,0.1 1.2,1.2
  region: -0.1,1.2 -1.2,1.2 -1.2,0.1 -0.1,0.1
  region: -0.1,-0.1 -1.2,-0.1 -1.2,-1.2 -0.1,-1.2
  rectangle: 0.1,-1.2 1.2,-0.1
Mechanical 13:
  circle w0.1: c-1.15,1.15 r0.5
  lines w0.1: -2.05,-2.05 -2.05,2.05 2.05,2.05 2.05,-2.05 -2.05,-2.05
Mechanical 15:
  lines w0.05: -2.2,-2.2 -2.2,2.2 2.2,2.2 2.2,-2.2 -2.2,-2.2
  lines w0.1: -0.5,0 0.5,0 ; 0,-0.5 0,0.5
3D body: height 0.8, standoff 0, extent -2.05,-2.05 2.05,2.05

## SRC14A [mm] "SON, 14-Leads, Body 6x5 mm, Pitch 0.8mm, NSC Recommended"
height 1
pads (15):
  rect 0.8x0.4 smd paste-0.2 mask+0.051: 1(-2.3,2.4) 2(-2.3,1.6) 3(-2.3,0.8) 4(-2.3,0) 5(-2.3,-0.8) 6(-2.3,-1.6) 7(-2.3,-2.4) 8(2.3,-2.4) 9(2.3,-1.6) 10(2.3,-0.8) 11(2.3,0) 12(2.3,0.8) 13(2.3,1.6) 14(2.3,2.4)
  rect 3.2x5 smd paste-1.6 mask+0.051: 15(0,0)
via 0.01,2.16 diameter 0.5 hole 0.2
via 0,-2.15 diameter 0.5 hole 0.2
via -1.3,0.825 diameter 0.5 hole 0.2
via 0,0.825 diameter 0.5 hole 0.2
via 1.3,0.825 diameter 0.5 hole 0.2
via -1.3,-0.825 diameter 0.5 hole 0.2
via 0,-0.825 diameter 0.5 hole 0.2
via 1.3,-0.825 diameter 0.5 hole 0.2
Top Overlay:
  circle w0.25: c-3.4,3.1 r0.125
  lines w0.2: -2.85,-3.2 -2.85,-3.1 ; -2.85,3.1 -2.85,3.2 ; -2.845,-3.2 -2.2,-3.2 ; -2.845,3.2 -2.2,3.2 ; 2.2,-3.2 2.845,-3.2 ; 2.2,3.2 2.845,3.2 ; 2.85,-3.2 2.85,-3.1 ; 2.85,3.1 2.85,3.2
Top Paste:
  region: 2.9,2.6 2,2.6 2,2.2 2.9,2.2
  region: 2.9,1.8 2,1.8 2,1.4 2.9,1.4
  region: 2.9,1 2,1 2,0.6 2.9,0.6
  region: 2.9,-0.6 2,-0.6 2,-1 2.9,-1
  region: 2.9,-1.4 2,-1.4 2,-1.8 2.9,-1.8
  region: 2.9,-2.2 2,-2.2 2,-2.6 2.9,-2.6
  rectangle: 2,-0.2 2.9,0.2
  region: -2,0.2 -2.9,0.2 -2.9,-0.2 -2,-0.2
  rectangle: -2.9,-2.6 -2,-2.2
  rectangle: -2.9,-1.8 -2,-1.4
  rectangle: -2.9,-1 -2,-0.6
  rectangle: -2.9,0.6 -2,1
  rectangle: -2.9,1.4 -2,1.8
  region: 1.5,0.7 0.1,0.7 0.1,-0.7 1.5,-0.7
  rectangle: -1.5,-0.7 -0.1,0.7
  region: 1.5,2.35 0.11,2.35 0.11,0.95 1.5,0.95
  rectangle: -1.5,0.95 -0.1,2.35
  region: 1.5,-0.95 0.1,-0.95 0.1,-2.35 1.5,-2.35
  rectangle: -1.5,-2.35 -0.1,-0.95
  rectangle: -2.9,2.2 -2,2.6
Mechanical 13:
  circle w0.1: c-1.65,2.15 r0.5
  lines w0.1: -2.55,-3.05 2.55,-3.05 2.55,3.05 -2.55,3.05 -2.55,-3.05
Mechanical 15:
  lines w0.05: -2.8,-3.15 2.8,-3.15 2.8,3.15 -2.8,3.15 -2.8,-3.15
  lines w0.1: -0.5,0 0.5,0 ; 0,-0.5 0,0.5
3D body: height 1, standoff 0, extent -2.549,-3.049 2.549,3.049

## T05A [mm] "TO, Thru-Hole, Vertical, Heatsink Mounted; 5 In-Line Leads; Pitch 1.70 mm"
height 19.6
pads (5):
  rect 1.4x2 hole 1.1: 1(-3.4,0)
  oval 1.4x2 hole 1.1: 2(-1.7,0) 3(0,0) 4(1.7,0) 5(3.4,0)
Top Overlay:
  circle w0.25: c-4.65,-1.45 r0.125
  lines w0.2: -5.3,2.3 5.3,2.3 ; -5.3,-2.1 5.3,-2.1 5.3,2.8 -5.3,2.8 -5.3,-2.1
Mechanical 13:
  lines w0.1: -5.3,2.3 5.3,2.3 ; -5.3,-2.1 -5.3,2.8 5.3,2.8 5.3,-2.1 -5.3,-2.1 ; -3.91,-0.28 -3.91,0.28 -2.89,0.28 -2.89,-0.28 -3.91,-0.28 ; -2.21,-0.28 -2.21,0.28 -1.19,0.28 -1.19,-0.28 -2.21,-0.28 ; -0.51,-0.28 -0.51,0.28 0.51,0.28 0.51,-0.28 -0.51,-0.28 ; 1.19,-0.28 1.19,0.28 2.21,0.28 2.21,-0.28 1.19,-0.28 ; 2.89,-0.28 2.89,0.28 3.91,0.28 3.91,-0.28 2.89,-0.28
Mechanical 15:
  lines w0.1: -0.5,0 0.5,0 ; 0,-0.5 0,0.5
3D body: height 13, standoff 4.1, extent -5.35,-2.15 5.35,2.85
3D body: height 19.6, standoff 13, extent -5.299,2.301 5.299,2.799
3D body: height 4.1, standoff 0, extent -3.909,-0.279 -2.891,0.279
3D body: height 4.1, standoff 0, extent -2.209,-0.279 -1.191,0.279
3D body: height 4.1, standoff 0, extent 1.191,-0.279 2.209,0.279
3D body: height 4.1, standoff 0, extent 2.891,-0.279 3.909,0.279
3D body: height 4.1, standoff 0, extent -0.509,-0.279 0.509,0.279

## T05D [mm] "TO, Thru-Hole, Vertical, Heatsink Mounted; 5 Bent Staggered Leads; Pitch 1.7 mm"
height 21.1
pads (5):
  rect 1.7x1.7 hole 1.1: 1(-3.4,-2)
  round 1.7 hole 1.1: 2(-1.7,2) 3(0,-2) 4(1.7,2) 5(3.4,-2)
Top Overlay:
  circle w0.25: c-4.8,-2 r0.125
  lines w0.2: -5.3,5.73 5.3,5.73 ; -3.854,1.53 -5.3,1.53 -5.3,6.23 5.3,6.23 5.3,1.53 3.854,1.53
Mechanical 13:
  lines w0.1: -5.3,4.93 5.3,4.93 ; -3.91,-1.685 -3.91,-2.315 -2.89,-2.315 -2.89,-1.685 ; -3.91,-1.685 -2.89,-1.685 ; -3.91,-1.685 -3.91,3.005 ; -3.91,3.005 -2.89,3.005 ; -3.91,3.005 -3.91,3.635 -2.89,3.635 -2.89,3.005 ; -2.89,-1.685 -2.89,3.005 ; -2.21,2.315 -2.21,1.685 -1.19,1.685 -1.19,2.315 ; -2.21,2.315 -1.19,2.315 ; -2.21,2.315 -2.21,3.005 ; -2.21,3.005 -1.19,3.005 ; -2.21,3.005 -2.21,3.635 -1.19,3.635 -1.19,3.005 ; -1.19,2.315 -1.19,3.005 ; -0.51,-1.685 -0.51,3.005 ; -0.51,-1.685 0.51,-1.685 ; -0.51,-1.685 -0.51,-2.315 0.51,-2.315 0.51,-1.685 ; -0.51,3.005 -0.51,3.635 0.51,3.635 0.51,3.005 ; -0.51,3.005 0.51,3.005 ; 0.51,-1.685 0.51,3.005 ; 1.19,2.315 1.19,1.685 2.21,1.685 2.21,2.315 ; 1.19,2.315 2.21,2.315 ; 1.19,2.315 1.19,3.005 ; 1.19,3.005 2.21,3.005 ; 1.19,3.005 1.19,3.635 2.21,3.635 2.21,3.005 ; 2.21,2.315 2.21,3.005 ; 2.89,-1.685 2.89,3.005 ; 2.89,-1.685 2.89,-2.315 3.91,-2.315 3.91,-1.685 ; 2.89,-1.685 3.91,-1.685 ; 2.89,3.005 3.91,3.005 ; 2.89,3.005 2.89,3.635 3.91,3.635 3.91,3.005 ; 3.91,-1.685 3.91,3.005 ; -5.3,1.53 -5.3,6.23 5.3,6.23 5.3,1.53 -5.3,1.53
Mechanical 15:
  lines w0.1: -0.5,0 0.5,0 ; 0,-0.5 0,0.5
3D body: height 5.6, standoff 1.95, extent -3.909,3.006 -2.891,3.634
3D body: height 1.72, standoff 0.63, extent 2.891,-1.684 3.909,1.529
3D body: height 1.72, standoff 0.63, extent -0.509,-1.684 0.509,1.529
3D body: height 1.72, standoff 0.63, extent -3.909,-1.684 -2.891,1.529
3D body: height 0.93, standoff 0, extent 2.891,-2.314 3.909,-1.686
3D body: height 0.93, standoff 0, extent -0.509,-2.314 0.509,-1.686
3D body: height 0.93, standoff 0, extent -3.909,-2.314 -2.891,-1.686
3D body: height 2.26, standoff 1.42, extent -0.509,1.531 0.509,3.004
3D body: height 2.26, standoff 1.42, extent -3.909,1.531 -2.891,3.004
3D body: height 2.26, standoff 1.42, extent 2.891,1.531 3.909,3.004
3D body: height 2.26, standoff 0.63, extent 1.191,2.316 2.209,3.004
3D body: height 2.26, standoff 0.63, extent -2.209,2.316 -1.191,3.004
3D body: height 0.93, standoff 0, extent -2.209,1.686 -1.191,2.314
3D body: height 0.93, standoff 0, extent 1.191,1.686 2.209,2.314
3D body: height 5.6, standoff 1.95, extent 2.891,3.006 3.909,3.634
3D body: height 5.6, standoff 1.95, extent 1.191,3.006 2.209,3.634
3D body: height 5.6, standoff 1.95, extent -0.509,3.006 0.509,3.634
3D body: height 5.6, standoff 1.95, extent -2.209,3.006 -1.191,3.634
3D body: height 14.5, standoff 5.6, extent -5.35,1.48 5.35,6.28
3D body: height 21.1, standoff 14.5, extent -5.299,4.931 5.299,6.229

## TA07B [mm] "TO, Thru-Hole, Vertical, Heatsink Mounted; 7 Bent Staggered Leads; Pitch 1.27 mm"
height 20.9
pads (7):
  rect 1.6x1.6 hole 1: 1(-3.81,-2.54)
  round 1.6 hole 1: 2(-2.54,2.54) 3(-1.27,-2.54) 4(0,2.54) 5(1.27,-2.54) 6(2.54,2.54) 7(3.81,-2.54)
Top Overlay:
  circle w0.25: c-5.16,-2.54 r0.125
  lines w0.2: -5.25,4.85 5.25,4.85 ; -4,0.67 -5.25,0.67 -5.25,5.35 5.25,5.35 5.25,0.67 4,0.67
Mechanical 13:
  lines w0.1: -5.25,4.05 5.25,4.05 ; -4.255,-2.26 -4.255,-2.82 -3.365,-2.82 -3.365,-2.26 ; -4.255,-2.26 -3.365,-2.26 ; -4.255,-2.26 -4.255,2.26 ; -4.255,2.26 -3.365,2.26 ; -4.255,2.26 -4.255,2.82 -3.365,2.82 -3.365,2.26 ; -3.365,-2.26 -3.365,2.26 ; -1.715,-2.26 -1.715,-2.82 -0.825,-2.82 -0.825,-2.26 ; -1.715,-2.26 -0.825,-2.26 ; -1.715,-2.26 -1.715,2.26 ; -1.715,2.26 -0.825,2.26 ; -1.715,2.26 -1.715,2.82 -0.825,2.82 -0.825,2.26 ; -0.825,-2.26 -0.825,2.26 ; 0.825,-2.26 0.825,-2.82 1.715,-2.82 1.715,-2.26 ; 0.825,-2.26 1.715,-2.26 ; 0.825,-2.26 0.825,2.26 ; 0.825,2.26 1.715,2.26 ; 0.825,2.26 0.825,2.82 1.715,2.82 1.715,2.26 ; 1.715,-2.26 1.715,2.26 ; 3.365,-2.26 3.365,2.26 ; 3.365,-2.26 3.365,-2.82 4.255,-2.82 4.255,-2.26 ; 3.365,-2.26 4.255,-2.26 ; 3.365,2.26 4.255,2.26 ; 3.365,2.26 3.365,2.82 4.255,2.82 4.255,2.26 ; 4.255,-2.26 4.255,2.26 ; -5.25,0.67 5.25,0.67 5.25,5.35 -5.25,5.35 -5.25,0.67 ; -2.985,2.26 -2.095,2.26 -2.095,2.82 -2.985,2.82 -2.985,2.26 ; -0.445,2.26 0.445,2.26 0.445,2.82 -0.445,2.82 -0.445,2.26 ; 2.095,2.26 2.985,2.26 2.985,2.82 2.095,2.82 2.095,2.26
Mechanical 15:
  lines w0.1: -0.5,0 0.5,0 ; 0,-0.5 0,0.5
3D body: height 20.9, standoff 14.35, extent -5.249,4.051 5.249,5.349
3D body: height 5.4, standoff 3.3, extent 0.826,2.261 1.714,2.819
3D body: height 5.4, standoff 3.3, extent 3.366,2.261 4.254,2.819
3D body: height 5.4, standoff 0, extent 2.096,2.261 2.984,2.819
3D body: height 5.4, standoff 0, extent -0.444,2.261 0.444,2.819
3D body: height 5.4, standoff 3.3, extent -4.254,2.261 -3.366,2.819
3D body: height 5.4, standoff 0, extent -2.984,2.261 -2.096,2.819
3D body: height 5.4, standoff 3.3, extent -1.714,2.261 -0.826,2.819
3D body: height 3.69, standoff 2.15, extent -4.254,0.671 -3.366,2.259
3D body: height 3.69, standoff 2.15, extent -1.714,0.671 -0.826,2.259
3D body: height 3.69, standoff 2.15, extent 0.826,0.671 1.714,2.259
3D body: height 3.69, standoff 2.15, extent 3.366,0.671 4.254,2.259
3D body: height 2.45, standoff 0.45, extent 3.366,-2.259 4.254,0.669
3D body: height 2.45, standoff 0.45, extent 0.826,-2.259 1.714,0.669
3D body: height 2.45, standoff 0.45, extent -4.254,-2.259 -3.366,0.669
3D body: height 2.45, standoff 0.45, extent -1.714,-2.259 -0.826,0.669
3D body: height 0.7, standoff 0, extent 0.826,-2.819 1.714,-2.261
3D body: height 0.7, standoff 0, extent -4.254,-2.819 -3.366,-2.261
3D body: height 0.7, standoff 0, extent -1.714,-2.819 -0.826,-2.261
3D body: height 0.7, standoff 0, extent 3.366,-2.819 4.254,-2.261
3D body: height 14.35, standoff 5.4, extent -5.3,0.62 5.3,5.4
